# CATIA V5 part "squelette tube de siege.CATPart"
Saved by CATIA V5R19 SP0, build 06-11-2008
Part number: squelette tube de siege
Publications: "Plan.1", "Plan.2", "Plan.3", "Droite.1", "Point.1", "Point.2", "Point.3", "Droite.2", "Droite.3", "Droite.4", "distance verticale entre les deux pivot", "position horizontale du pivot en haut", "hauteur du cube", "hauteur du tube", "distance entre pivot en bas et le fond", "epaisseur du pivot en haut", "demi_distance entre pivots en haut", "rayon du tube", "demi_largeur de l'oreille"
Bounding box of the stored display mesh (mm): x -23 to 0, y 0 to 40, z 0 to 165
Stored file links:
  I:\yyang\yyang\squelette tube de siege.CATPart
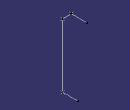
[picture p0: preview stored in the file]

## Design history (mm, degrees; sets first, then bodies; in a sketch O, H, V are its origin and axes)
Parameters
  `distance verticale entre les deux pivot` = 165 mm
  `position horizontale du pivot en haut` = 23 mm
  `hauteur du cube` = 40 mm
  `hauteur du tube` = 150 mm
  `distance entre pivot en bas et le fond` = 10 mm
  `epaisseur du pivot en haut` = 3 mm
  `demi_distance entre pivots en haut` = 11 mm
  `rayon du tube` = 12 mm
  `demi_largeur de l'oreille` = 7.5 mm
Body1 (main body)
  Plane1: type Offset, Offset 0, RefPlane xy-plane
  Plane2: type Offset, Offset 0, RefPlane yz-plane
  Plane3: type Offset, Offset 0, RefPlane zx-plane
  Point1: (0, 0, 0)
  Point2: (0, 0, 165 {= `distance verticale entre les deux pivot`})
  Line1: type PtPt, SecondPoint Point2, FirstPoint Point1
  Point3: (-23 {= -`position horizontale du pivot en haut`}, 0, 0), relative to Point2
  Line2: type PtPt, SecondPoint Point2, FirstPoint Point3
  Line3: type PtDir, Direction (0, 1, 0), Start 0, End 40, RefPoint Point3
  Line4: type PtDir, Direction (0, 1, 0), Start 0, End 40, RefPoint Point1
